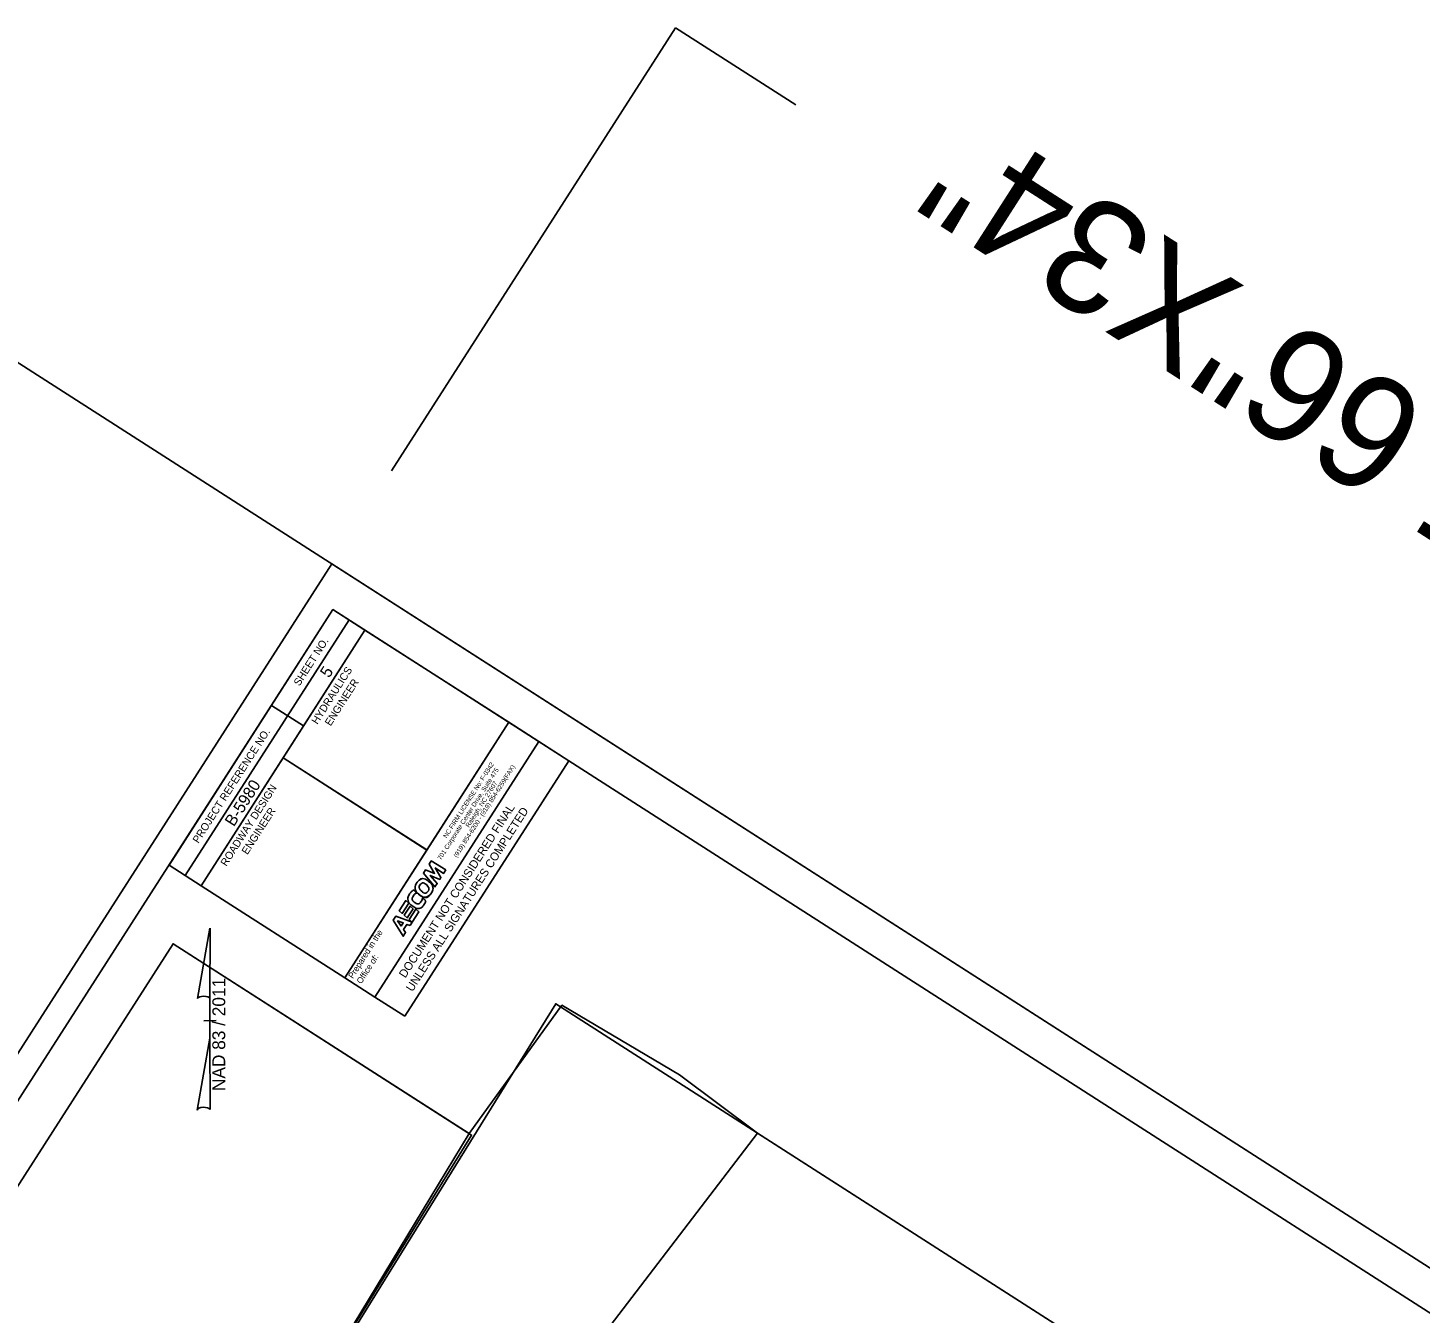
# Model space of a CAD drawing. Extents: x 2346049 to 2349719, y 842061 to 846435.
# Drawn here: x 2347884 to 2348801, y 845588 to 846435 of the extents above; entities that cross this region are included whole.
import ezdxf

# ---------------------------------------------------------------- set-up
doc = ezdxf.new("R2010")
doc.units = 0
for name, color, linetype in [('Default', 7, 'Continuous'), ('Old_Level_49', 7, 'Continuous'), ('Prop North Arrow NAD83 for Plan Sheets CELL', 7, 'Continuous'), ('Scratch_Level_0', 7, 'Continuous'), ('Sheet Data Field CELL', 7, 'Continuous'), ('Sheet Detail CELL', 7, 'Continuous'), ('Sheet Plot Border Inside CELL', 7, 'Continuous'), ('Sheet Plot Border Outside CELL', 7, 'Continuous'), ('Sheet Profile CELL', 7, 'Continuous'), ('Sheet Sticker Exception Certification CELL', 7, 'Continuous')]:
    doc.layers.add(name, color=color, linetype=linetype)

# ---------------------------------------------------------------- blocks, each defined once
blk = doc.blocks.new('block 2')
at = {"layer": 'Default'}
for p, q in [((0.10234, 0.09375), (0.10197, 0.09133)), ((0.10966, 0.09375), (0.10234, 0.09375)), ((0.10929, 0.09133), (0.10966, 0.09375)), ((0.10114, 0.08576), (0.10078, 0.08333)), ((0.10846, 0.08576), (0.10114, 0.08576)), ((0.10137, 0.08733), (0.10174, 0.08975)), ((0.10782, 0.08733), (0.10137, 0.08733)), ((0.10174, 0.08975), (0.10818, 0.08975)), ((0.10197, 0.09133), (0.10929, 0.09133)), ((0.10818, 0.08975), (0.10782, 0.08733)), ((0.1081, 0.08333), (0.10846, 0.08576)), ((0.10078, 0.08333), (0.1081, 0.08333))]:
    blk.add_line(p, q, dxfattribs=at)
for points in [[(0.10929, 0.09133), (0.10197, 0.09133), (0.10234, 0.09375), (0.10966, 0.09375), (0.10929, 0.09133)], [(0.10846, 0.08576), (0.10114, 0.08576), (0.10078, 0.08333), (0.1081, 0.08333), (0.10846, 0.08576)], [(0.10782, 0.08733), (0.10137, 0.08733), (0.10174, 0.08975), (0.10818, 0.08975), (0.10782, 0.08733)]]:
    blk.add_lwpolyline(points, dxfattribs=at)
blk = doc.blocks.new('block 3')
at = {"layer": 'Default'}
blk.add_open_spline([(0.12275, 0.09393), (0.12554, 0.09373), (0.12726, 0.09146), (0.12695, 0.08843), (0.12663, 0.08531), (0.12411, 0.08298), (0.12127, 0.08318), (0.11848, 0.08338), (0.11676, 0.08565), (0.11707, 0.08868), (0.11739, 0.0918), (0.11991, 0.09413), (0.12275, 0.09393)], degree=3, dxfattribs=at)

msp = doc.modelspace()

# ---------------------------------------------------------------- linework, layer by layer
at = {"layer": 'Old_Level_49'}
for p, q in [((2348149.5, 845886.48), (2348148.13, 845884.34)), ((2348148.13, 845884.34), (2348151.73, 845878.15)), ((2348159.13, 845880.56), (2348149.5, 845886.48)), ((2348155.87, 845875.47), (2348152.09, 845881.83)), ((2348152.09, 845881.83), (2348157.63, 845878.23)), ((2348145.66, 845880.48), (2348144.28, 845878.34)), ((2348144.28, 845878.34), (2348151.9, 845869.29)), ((2348151.73, 845878.15), (2348145.66, 845880.48)), ((2348153.41, 845871.65), (2348148.88, 845876.83)), ((2348148.88, 845876.83), (2348155.09, 845874.27)), ((2348151.9, 845869.29), (2348153.41, 845871.65)), ((2348155.09, 845874.27), (2348155.87, 845875.47)), ((2348157.63, 845878.23), (2348159.13, 845880.56)), ((2348126.1, 845849.99), (2348124.45, 845847.41)), ((2348124.45, 845847.41), (2348131.09, 845836.84)), ((2348137.02, 845846.09), (2348126.1, 845849.99)), ((2348127.32, 845846.91), (2348127.33, 845846.94)), ((2348129.73, 845843.42), (2348127.32, 845846.91)), ((2348127.33, 845846.94), (2348131.08, 845845.52)), ((2348131.08, 845845.52), (2348129.73, 845843.42)), ((2348131.27, 845841.2), (2348133.46, 845844.62)), ((2348133.46, 845844.62), (2348135.57, 845843.83)), ((2348135.57, 845843.83), (2348137.02, 845846.09)), ((2348131.09, 845836.84), (2348132.62, 845839.23)), ((2348132.62, 845839.23), (2348131.27, 845841.2))]:
    msp.add_line(p, q, dxfattribs=at)
for points in [[(2348159.13, 845880.56), (2348149.5, 845886.48), (2348148.13, 845884.34), (2348151.73, 845878.15), (2348145.66, 845880.48), (2348144.28, 845878.34), (2348151.9, 845869.29), (2348153.41, 845871.65), (2348148.88, 845876.83), (2348155.09, 845874.27), (2348155.87, 845875.47), (2348152.09, 845881.83), (2348157.63, 845878.23), (2348159.13, 845880.56)], [(2348135.57, 845843.83), (2348137.02, 845846.09), (2348126.1, 845849.99), (2348124.45, 845847.41), (2348131.09, 845836.84), (2348132.62, 845839.23), (2348131.27, 845841.2), (2348133.46, 845844.62), (2348135.57, 845843.83)], [(2348129.73, 845843.42), (2348127.32, 845846.91), (2348127.33, 845846.94), (2348131.08, 845845.52), (2348129.73, 845843.42)]]:
    msp.add_lwpolyline(points, dxfattribs=at)
for points in [[(2348148.35, 845863.84), (2348146.51, 845862.26), (2348143.91, 845862.32), (2348141.68, 845864.1), (2348139.02, 845866.22), (2348138.37, 845869.89), (2348140.22, 845872.36)], [(2348140.22, 845872.36), (2348142.03, 845874.79), (2348145.11, 845875.04), (2348147.7, 845872.98), (2348150.36, 845870.85), (2348151.01, 845867.19), (2348149.16, 845864.71), (2348148.91, 845864.38), (2348148.64, 845864.09), (2348148.35, 845863.84)], [(2348146.48, 845870.57), (2348145.09, 845871.94), (2348143.45, 845872.15), (2348142.43, 845871.09), (2348141.3, 845869.93), (2348141.54, 845868.06), (2348143, 845866.6), (2348144.39, 845865.23), (2348146.03, 845865.02), (2348147.05, 845866.08), (2348148.19, 845867.24), (2348147.94, 845869.11), (2348146.48, 845870.57)], [(2348146.48, 845870.57), (2348145.09, 845871.94), (2348143.45, 845872.15), (2348142.43, 845871.09), (2348141.3, 845869.93), (2348141.54, 845868.06), (2348143, 845866.6), (2348144.39, 845865.23), (2348146.03, 845865.02), (2348147.05, 845866.08), (2348148.19, 845867.24), (2348147.94, 845869.11), (2348146.48, 845870.57)], [(2348143.81, 845862.04), (2348143.69, 845861.21), (2348143.13, 845860.23), (2348142.83, 845859.76), (2348141.87, 845858.26), (2348140.2, 845857.92), (2348138.71, 845858.95), (2348137.13, 845860.03), (2348136.75, 845861.99), (2348137.82, 845863.65), (2348138.32, 845864.43), (2348139.02, 845864.95), (2348139.94, 845865.24), (2348139.94, 845865.24), (2348137.95, 845867.15), (2348137.95, 845867.15), (2348136.79, 845866.57), (2348136.05, 845865.92), (2348135.42, 845864.93), (2348133.66, 845862.19), (2348134.49, 845858.47), (2348137.3, 845856.53), (2348140.02, 845854.66), (2348143.13, 845855.21), (2348144.86, 845857.9), (2348145.16, 845858.36), (2348145.75, 845859.4), (2348145.87, 845860.23), (2348145.87, 845860.23), (2348143.81, 845862.04), (2348143.81, 845862.04)], [(2348143.81, 845862.04), (2348143.69, 845861.21), (2348143.13, 845860.23), (2348142.83, 845859.76), (2348141.87, 845858.26), (2348140.2, 845857.92), (2348138.71, 845858.95), (2348137.13, 845860.03), (2348136.75, 845861.99), (2348137.82, 845863.65), (2348138.32, 845864.43), (2348139.02, 845864.95), (2348139.94, 845865.24), (2348139.94, 845865.24), (2348137.95, 845867.15), (2348137.95, 845867.15), (2348136.79, 845866.57), (2348136.05, 845865.92), (2348135.42, 845864.93), (2348133.66, 845862.19), (2348134.49, 845858.47), (2348137.3, 845856.53), (2348140.02, 845854.66), (2348143.13, 845855.21), (2348144.86, 845857.9), (2348145.16, 845858.36), (2348145.75, 845859.4), (2348145.87, 845860.23), (2348145.87, 845860.23), (2348143.81, 845862.04), (2348143.81, 845862.04)]]:
    msp.add_open_spline(points, degree=3, dxfattribs=at)
at = {"layer": 'Prop North Arrow NAD83 for Plan Sheets CELL'}
for p, q in [((2347995.43, 845795.77), (2348003.65, 845842.18)), ((2348003.7, 845842.18), (2348003.68, 845794.38)), ((2348003.67, 845769.58), (2348003.68, 845795.78)), ((2348003.68, 845794.38), (2348003.68, 845795.73)), ((2347999.67, 845781.15), (2347999.62, 845781.15)), ((2348003.22, 845781.18), (2347999.67, 845781.15)), ((2347999.72, 845781.15), (2348007.72, 845781.22)), ((2348003.67, 845769.58), (2347995.3, 845722.27)), ((2348003.7, 845722.53), (2348003.67, 845769.58))]:
    msp.add_line(p, q, dxfattribs=at)
for centre, start_param, end_param in [((2347999.56, 845795.3), 0.211319, 2.90315), ((2347999.53, 845722.13), 0.19626, 3.136524)]:
    msp.add_ellipse(centre, major_axis=(4.23, 0.01), ratio=0.461128, start_param=start_param, end_param=end_param, dxfattribs=at)
at = {"layer": 'Scratch_Level_0'}
for points in [[(2347004.98, 844312.52), (2347188.19, 844598.2), (2347979.34, 845831.88), (2348174.51, 845706.72), (2348063.34, 845523.06), (2348169.55, 845452.17), (2348364.46, 845707.02), (2348364.46, 845707.02), (2348364.46, 845707.02), (2349350.39, 845074.75), (2349350.39, 845074.75), (2349350.39, 845074.75), (2348851.77, 844297.24)], [(2347004.98, 844312.52), (2347188.19, 844598.2), (2347979.34, 845831.88), (2348174.51, 845706.72), (2348235.63, 845791.33), (2348313.03, 845745.35), (2348364.46, 845707.02), (2348364.46, 845707.02), (2348364.46, 845707.02), (2349350.39, 845074.75), (2349350.39, 845074.75), (2349350.39, 845074.75), (2348851.77, 844297.24)], [(2347188.19, 844598.2), (2347405.07, 844503.52), (2347561.13, 844746.87), (2347567.31, 844745.85), (2347676.96, 844903.79), (2347773.04, 845052.54), (2348176.04, 845705.73), (2347979.34, 845831.88), (2347188.19, 844598.2)], [(2346937.85, 844263.64), (2347160.22, 844610.4), (2347405.07, 844503.52), (2347561.13, 844746.87), (2347567.31, 844745.85), (2347676.96, 844903.79), (2347773.04, 845052.54), (2348231.54, 845792.27), (2348231.54, 845792.27), (2348231.54, 845792.27), (2349350.39, 845074.75), (2349350.39, 845074.75), (2349350.39, 845074.75), (2348851.77, 844297.24)]]:
    msp.add_lwpolyline(points, dxfattribs=at)
msp.add_lwpolyline([(2347188.19, 844598.2), (2347405.07, 844503.52), (2347561.13, 844746.87), (2347567.31, 844745.85), (2347676.96, 844903.79), (2347773.04, 845052.54), (2348176.04, 845705.73), (2347979.34, 845831.88)], close=True, dxfattribs=at)
at = {"layer": 'Sheet Detail CELL'}
for p, q in [((2348123.23, 846143.55), (2348310.41, 846435.43)), ((2348310.41, 846435.43), (2348389.67, 846384.61)), ((2347987.31, 845876.87), (2348095.31, 846045.27)), ((2347997.84, 845870.12), (2348105.83, 846038.52)), ((2347997.84, 845870.12), (2348105.83, 846038.52)), ((2348044.3, 845988.88), (2348065.34, 845975.39)), ((2348051.85, 845954.34), (2348146.5, 845893.64))]:
    msp.add_line(p, q, dxfattribs=at)
for points in [[(2346465.26, 843526.72), (2348084.74, 846052.04), (2349473.67, 845161.33), (2347854.19, 842636)], [(2347976.75, 845883.65), (2348084.74, 846052.04), (2348105.83, 846038.52), (2347997.84, 845870.12)], [(2348051.85, 845954.34), (2348105.83, 846038.52), (2348200.53, 845977.79), (2348146.55, 845893.61)], [(2347997.84, 845870.12), (2348051.85, 845954.34), (2348146.55, 845893.61), (2348092.54, 845809.39)]]:
    msp.add_lwpolyline(points, close=True, dxfattribs=at)
at = {"layer": 'Sheet Plot Border Inside CELL'}
msp.add_lwpolyline([(2348083.93, 846082.26), (2346302.5, 843304.4), (2347720.05, 842395.34), (2349501.48, 845173.2)], close=True, dxfattribs=at)
at = {"layer": 'Sheet Plot Border Outside CELL'}
msp.add_lwpolyline([(2347866.79, 846221.51), (2346048.65, 843386.41), (2347900.52, 842198.82), (2349718.66, 845033.92)], close=True, dxfattribs=at)
at = {"layer": 'Sheet Profile CELL'}
msp.add_line((2348092.54, 845809.39), (2348112.32, 845796.71), dxfattribs=at)
at = {"layer": 'Sheet Sticker Exception Certification CELL'}
for p, q in [((2348092.54, 845809.39), (2348200.52, 845977.78)), ((2348200.53, 845977.77), (2348220.31, 845965.09)), ((2348220.3, 845965.09), (2348112.32, 845796.71)), ((2348112.32, 845796.71), (2348220.3, 845965.09)), ((2348220.31, 845965.09), (2348240.1, 845952.4)), ((2348240.09, 845952.41), (2348132.1, 845784.02)), ((2348112.32, 845796.71), (2348092.54, 845809.39)), ((2348132.1, 845784.02), (2348112.32, 845796.71))]:
    msp.add_line(p, q, dxfattribs=at)

# ---------------------------------------------------------------- block references
at = {"layer": 'Old_Level_49', "xscale": 1084.8432715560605, "yscale": 1084.8432715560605, "rotation": 57.32454195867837}
for name in ['block 3', 'block 2']:
    msp.add_blockref(name, (2348154.09, 845705.26), dxfattribs=at)

# ---------------------------------------------------------------- texts
at = {"layer": 'Old_Level_49'}
for s, height, p in [('701 Corporate Center Drive, Suite 475', 3.0135, (2348155.88, 845886.74)), ('NC FIRM LICENSE No: F-0342', 3.0135, (2348159.62, 845901.15)), ('(919) 854-6200 - (919) 854-6259(FAX)', 3.0135, (2348166.43, 845888.37)), ('Raleigh, NC 27607', 3.0135, (2348174.38, 845908.16)), ('Prepared in the ', 4.0179, (2348097.88, 845808.55)), ('Office of:', 4.018, (2348103.38, 845805.03))]:
    msp.add_text(s, height=height, rotation=57.32454, dxfattribs=at).set_placement(p)
at = {"layer": 'Prop North Arrow NAD83 for Plan Sheets CELL'}
msp.add_text('NAD 83 / 2011', height=8.5013, rotation=89.97611, dxfattribs=at).set_placement((2348013.71, 845734.78))
at = {"layer": 'Sheet Data Field CELL'}
for s, p in [('5', (2348082.19, 846006.56)), ('B-5980', (2348019.4, 845908.56))]:
    msp.add_text(s, height=7.75, rotation=57.32812, dxfattribs=at).set_placement(p)
at = {"layer": 'Sheet Detail CELL'}
for s, height, rotation, p in [('TO PLOT FULL SIZE 66"X34"', 75, 147.32812, (2349636.49, 845655.47)), ('SHEET NO.', 5, 57.32812, (2348062.62, 846001.25)), ('HYDRAULICS', 5, 57.32812, (2348074.43, 845976.03)), ('ENGINEER', 5, 57.32812, (2348083.17, 845974.94)), ('PROJECT REFERENCE NO.', 5.0001, 57.32812, (2347996.06, 845897.64)), ('ROADWAY DESIGN', 5.0001, 57.32812, (2348014.45, 845882.51)), ('ENGINEER', 5, 57.32812, (2348028.34, 845890.18))]:
    msp.add_text(s, height=height, rotation=rotation, dxfattribs=at).set_placement(p)
at = {"layer": 'Sheet Sticker Exception Certification CELL'}
for s, p in [('DOCUMENT NOT CONSIDERED FINAL', (2348132.4, 845808.86)), ('UNLESS ALL SIGNATURES COMPLETED', (2348137.07, 845799.84))]:
    msp.add_text(s, height=5.5, rotation=57.32812, dxfattribs=at).set_placement(p)

doc.saveas('drawing.dxf')
